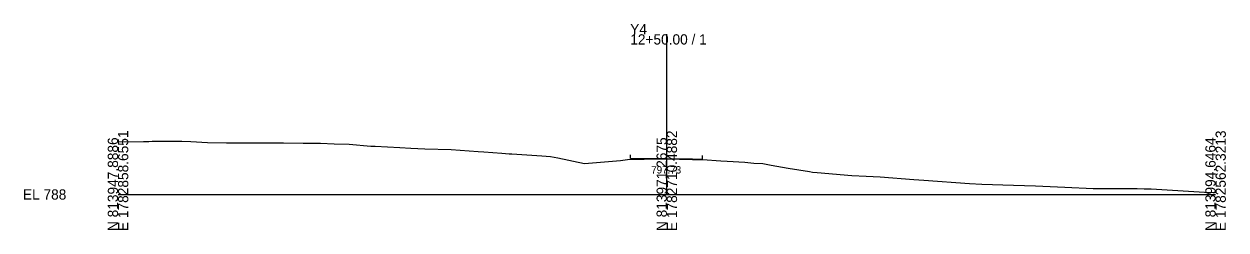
# Model space of a CAD drawing. Extents: x -26 to 3903, y -10 to 9562.
# Drawn here: x -25.7 to 302.8, y 4490.3 to 4546.6 of the extents above; entities that cross this region are included whole.
import ezdxf

# ---------------------------------------------------------------- set-up
doc = ezdxf.new("R2010")
doc.units = 0
for name, color, linetype in [('Exist Cross Section Cell', 7, 'Continuous'), ('Exist XS Center Line Elevation Label', 7, 'Continuous'), ('Exist XS Ground Line', 7, 'Continuous'), ('Prop XS EOT Tick Mark', 7, 'Continuous'), ('Prop XS Finish Grade Pavement', 7, 'Continuous')]:
    doc.layers.add(name, color=color, linetype=linetype)

msp = doc.modelspace()

# ---------------------------------------------------------------- linework, layer by layer
at = {"layer": 'Exist Cross Section Cell'}
for p, q in [((150, 4500), (150, 4543.77)), ((0, 4500), (150, 4500)), ((150, 4500), (300, 4500))]:
    msp.add_line(p, q, dxfattribs=at)
at = {"layer": 'Exist XS Ground Line'}
for p, q in [((0, 4514.42), (7, 4514.5)), ((7, 4514.5), (8.46, 4514.51)), ((8.46, 4514.51), (9.32, 4514.52)), ((9.32, 4514.52), (11.48, 4514.55)), ((11.48, 4514.55), (17.4, 4514.59)), ((17.4, 4514.59), (19.87, 4514.43)), ((19.87, 4514.43), (24.46, 4514.18)), ((24.46, 4514.18), (29.66, 4514.14)), ((29.66, 4514.14), (34.28, 4514.12)), ((34.28, 4514.12), (39.66, 4514.09)), ((39.66, 4514.09), (45.19, 4514.09)), ((45.19, 4514.09), (50.6, 4514.02)), ((50.6, 4514.02), (55.34, 4514.02)), ((55.34, 4514.02), (59.09, 4513.88)), ((59.09, 4513.88), (63.22, 4513.73)), ((63.22, 4513.73), (69.06, 4513.23)), ((69.06, 4513.23), (70.28, 4513.16)), ((70.28, 4513.16), (77.04, 4512.83)), ((77.04, 4512.83), (80.02, 4512.69)), ((80.02, 4512.69), (83.86, 4512.51)), ((83.86, 4512.51), (91.03, 4512.28)), ((91.03, 4512.28), (98.43, 4511.76)), ((98.43, 4511.76), (99.99, 4511.68)), ((99.99, 4511.68), (104.88, 4511.3)), ((104.88, 4511.3), (106.88, 4511.15)), ((106.88, 4511.15), (107.63, 4511.1)), ((107.63, 4511.1), (115.8, 4510.6)), ((115.8, 4510.6), (118.17, 4510.37)), ((118.17, 4510.37), (120.19, 4509.97)), ((120.19, 4509.97), (127.54, 4508.5)), ((127.54, 4508.5), (137.33, 4509.3)), ((137.33, 4509.3), (139.26, 4509.59)), ((139.26, 4509.59), (140.1, 4509.68)), ((140.1, 4509.68), (143.83, 4509.67)), ((143.83, 4509.67), (149.92, 4509.73)), ((149.92, 4509.73), (157, 4509.58)), ((157, 4509.58), (159.73, 4509.52)), ((159.73, 4509.52), (164.79, 4509.22)), ((164.79, 4509.22), (166.49, 4509.13)), ((166.49, 4509.13), (171.32, 4508.83)), ((171.32, 4508.83), (173.8, 4508.56)), ((173.8, 4508.56), (176.28, 4508.42)), ((176.28, 4508.42), (178.53, 4507.97)), ((178.53, 4507.97), (183.18, 4507.22)), ((183.18, 4507.22), (189, 4506.27)), ((189, 4506.27), (189.87, 4506.09)), ((189.87, 4506.09), (191.09, 4506.02)), ((191.09, 4506.02), (200.57, 4505.21)), ((200.57, 4505.21), (204.48, 4504.97)), ((204.48, 4504.97), (208.3, 4504.85)), ((208.3, 4504.85), (217.49, 4504.09)), ((217.49, 4504.09), (220.27, 4503.88)), ((220.27, 4503.88), (232.77, 4503)), ((232.77, 4503), (236.08, 4502.83)), ((236.08, 4502.83), (244.75, 4502.55)), ((244.75, 4502.55), (250.8, 4502.32)), ((250.8, 4502.32), (258.82, 4501.97)), ((258.82, 4501.97), (266.57, 4501.67)), ((266.57, 4501.67), (278.55, 4501.61)), ((278.55, 4501.61), (280.48, 4501.57)), ((280.48, 4501.57), (282.4, 4501.52)), ((282.4, 4501.52), (296.98, 4500.67)), ((296.98, 4500.67), (300, 4500.5))]:
    msp.add_line(p, q, dxfattribs=at)
at = {"layer": 'Prop XS EOT Tick Mark'}
for p, q in [((140.1, 4509.81), (140.1, 4510.81)), ((159.73, 4509.64), (159.73, 4510.64))]:
    msp.add_line(p, q, dxfattribs=at)
at = {"layer": 'Prop XS Finish Grade Pavement'}
for p, q in [((140.1, 4509.81), (143.83, 4509.8)), ((143.83, 4509.8), (149.92, 4509.86)), ((149.92, 4509.86), (157, 4509.7)), ((157, 4509.7), (159.73, 4509.64))]:
    msp.add_line(p, q, dxfattribs=at)

# ---------------------------------------------------------------- texts
at = {"layer": 'Exist Cross Section Cell'}
for s, p in [('Y4', (140, 4543.77)), ('12+50.00 / 1', (140, 4540.97)), ('EL 788', (-26, 4498.6))]:
    msp.add_text(s, height=2.8, dxfattribs=at).set_placement(p)
for s, p in [('N 813947.8886', (0, 4490)), ('E 1782858.6551', (2.8, 4490)), ('N 813971.2675', (150, 4490)), ('E 1782710.4882', (152.8, 4490)), ('N 813994.6464', (300, 4490)), ('E 1782562.3213', (302.8, 4490))]:
    msp.add_text(s, height=2.8, rotation=90, dxfattribs=at).set_placement(p)
at = {"layer": 'Exist XS Center Line Elevation Label'}
msp.add_text('797.73', height=2, dxfattribs=at).set_placement((145.75, 4505.73))

doc.saveas('drawing.dxf')
